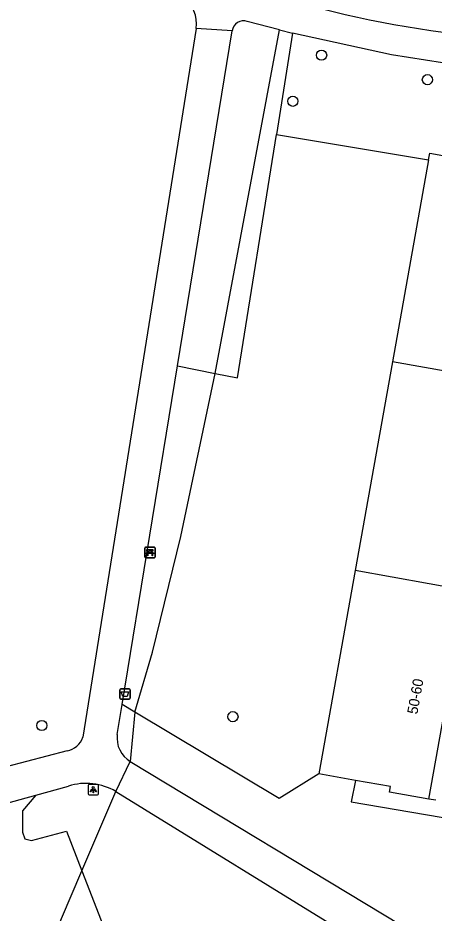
# Model space of a CAD drawing. Extents: x 161402 to 161933, y 381650 to 382313.
# Drawn here: x 161719.2 to 161759.2, y 381796.3 to 381882.3 of the extents above; entities that cross this region are included whole.
import ezdxf

# ---------------------------------------------------------------- set-up
doc = ezdxf.new("R2010")
doc.units = 0
for name, color, linetype in [('IMGEO_Afvalbak', 7, 'Continuous'), ('IMGEO_Bank', 7, 'Continuous'), ('IMGEO_Boom', 7, 'Continuous'), ('IMGEO_Groenvoorziening', 7, 'Continuous'), ('IMGEO_Lichtpunt', 7, 'Continuous'), ('IMGEO_Pand', 7, 'Continuous'), ('IMGEO_Pand_nummerreeks', 7, 'Continuous'), ('IMGEO_Voetpad_gesloten', 7, 'Continuous'), ('IMGEO_Voetpad_open', 7, 'Continuous')]:
    doc.layers.add(name, color=color, linetype=linetype)

msp = doc.modelspace()

# ---------------------------------------------------------------- linework, layer by layer
at = {"layer": 'IMGEO_Afvalbak'}
for p, q in [((161729.01, 381816.99), (161729.01, 381817.79)), ((161729.01, 381817.79), (161729.01, 381816.99)), ((161729.11, 381817.89), (161729.9, 381817.89)), ((161729.9, 381817.89), (161729.11, 381817.89)), ((161730, 381817.79), (161730, 381816.99)), ((161730, 381816.99), (161730, 381817.79)), ((161729.9, 381816.89), (161729.11, 381816.89)), ((161729.11, 381816.89), (161729.9, 381816.89))]:
    msp.add_line(p, q, dxfattribs=at)
msp.add_lwpolyline([(161729.153, 381817.604), (161729.857, 381817.604), (161729.708, 381817.134), (161729.302, 381817.134), (161729.153, 381817.604)], dxfattribs=at)
for centre, start, end in [((161729.11, 381817.79), 90, 180), ((161729.11, 381817.79), 90, 180), ((161729.9, 381817.79), 0, 90), ((161729.9, 381817.79), 360, 90), ((161729.11, 381816.99), 180, 270), ((161729.11, 381816.99), 180, 270), ((161729.9, 381816.99), 270, 0), ((161729.9, 381816.99), 270, 0)]:
    msp.add_arc(centre, 0.1, start, end, dxfattribs=at)
at = {"layer": 'IMGEO_Bank'}
for p, q in [((161731.478, 381831.472), (161732.319, 381831.472)), ((161732.319, 381831.472), (161731.478, 381831.472)), ((161731.403, 381830.547), (161731.403, 381831.388)), ((161731.403, 381831.388), (161731.403, 381830.547)), ((161732.1, 381830.87), (161731.707, 381830.87)), ((161731.712, 381830.978), (161731.712, 381831.084)), ((161731.756, 381831.084), (161731.756, 381830.978)), ((161732.044, 381831.09), (161731.762, 381831.09)), ((161731.762, 381830.972), (161732.044, 381830.972)), ((161732.05, 381830.978), (161732.05, 381831.084)), ((161732.094, 381831.084), (161732.094, 381830.978)), ((161732.403, 381831.397), (161732.403, 381830.556)), ((161732.403, 381830.556), (161732.403, 381831.397)), ((161732.328, 381830.472), (161731.487, 381830.472)), ((161731.487, 381830.472), (161732.328, 381830.472))]:
    msp.add_line(p, q, dxfattribs=at)
for points in [[(161731.65, 381830.87), (161731.508, 381830.87), (161731.62, 381830.972), (161731.706, 381830.972)], [(161731.706, 381831.09), (161731.62, 381831.09), (161731.62, 381831.251), (161732.183, 381831.251), (161732.183, 381831.09), (161732.1, 381831.09)], [(161731.7, 381830.863), (161731.7, 381830.656), (161731.657, 381830.656), (161731.657, 381830.863)], [(161732.1, 381830.972), (161732.183, 381830.972), (161732.295, 381830.87), (161732.156, 381830.87)], [(161732.15, 381830.863), (161732.15, 381830.656), (161732.106, 381830.656), (161732.106, 381830.863)]]:
    msp.add_lwpolyline(points, dxfattribs=at)
for centre, radius, start, end in [((161731.481, 381831.394), 0.0779, 92.4484, 184.28452), ((161731.481, 381831.394), 0.0779, 92.4484, 184.28452), ((161732.325, 381831.394), 0.0779, 2.4484, 94.28452), ((161732.325, 381831.394), 0.0779, 2.4484, 94.28452), ((161731.481, 381830.55), 0.0779, 182.4484, 274.28452), ((161731.481, 381830.55), 0.0779, 182.4484, 274.28452), ((161731.65, 381830.863), 0.00671, 2.89567, 87.10433), ((161731.707, 381830.863), 0.00671, 92.89567, 177.10433), ((161731.705, 381831.083), 0.00671, 2.89567, 87.10433), ((161731.705, 381830.979), 0.00671, 272.89567, 357.10433), ((161731.762, 381831.083), 0.00671, 92.89567, 177.10433), ((161731.762, 381830.979), 0.00671, 182.89567, 267.10433), ((161732.044, 381831.083), 0.00671, 2.89567, 87.10433), ((161732.044, 381830.979), 0.00671, 272.89567, 357.10433), ((161732.101, 381831.083), 0.00671, 92.89567, 177.10433), ((161732.101, 381830.979), 0.00671, 182.89567, 267.10433), ((161732.099, 381830.863), 0.00671, 2.89567, 87.10433), ((161732.156, 381830.863), 0.00671, 92.89567, 177.10433), ((161732.325, 381830.55), 0.0779, 272.4484, 4.28452), ((161732.325, 381830.55), 0.0779, 272.4484, 4.28452)]:
    msp.add_arc(centre, radius, start, end, dxfattribs=at)
at = {"layer": 'IMGEO_Boom'}
for centre in [(161748.379, 381878.735), (161758.532, 381876.381), (161745.615, 381874.307), (161739.871, 381815.204), (161721.521, 381814.349)]:
    msp.add_circle(centre, 0.489, dxfattribs=at)
at = {"layer": 'IMGEO_Groenvoorziening'}
for points in [[(161738.162, 381848.165), (161744.341, 381881.177)], [(161745.595, 381880.853), (161744.038, 381871.1)], [(161738.162, 381848.165), (161740.308, 381847.736), (161744.038, 381871.1)], [(161744.038, 381871.1), (161758.643, 381868.683)], [(161734.546, 381848.887), (161738.162, 381848.165)], [(161730.467, 381815.628), (161732.138, 381821.401), (161734.863, 381832.495), (161738.162, 381848.165)], [(161730.467, 381815.628), (161729.238, 381816.363)], [(161730.467, 381815.628), (161730.018, 381810.901)], [(161748.122, 381809.717), (161744.303, 381807.358), (161730.467, 381815.628)], [(161720.944, 381807.67), (161719.659, 381806.175), (161719.659, 381804.119), (161719.883, 381803.471), (161720.531, 381803.314), (161723.882, 381804.205), (161725.367, 381800.387)], [(161725.367, 381800.387), (161728.625, 381808.023)], [(161702.23, 381724.444), (161705.894, 381734.943), (161712.581, 381759.611), (161715.357, 381771.588), (161718.107, 381785.811), (161721.564, 381791.006), (161723.418, 381795.819), (161725.367, 381800.387)], [(161725.367, 381800.387), (161728.333, 381792.761), (161720.782, 381750), (161715.379, 381719.409), (161702.956, 381716.799)]]:
    msp.add_lwpolyline(points, dxfattribs=at)
at = {"layer": 'IMGEO_Lichtpunt'}
for p, q in [((161725.964, 381808.599), (161725.964, 381807.792)), ((161725.964, 381808.599), (161725.964, 381807.792)), ((161726.866, 381808.694), (161726.058, 381808.694)), ((161726.866, 381808.694), (161726.058, 381808.694)), ((161726.96, 381807.792), (161726.96, 381808.599)), ((161726.96, 381807.792), (161726.96, 381808.599)), ((161726.058, 381807.698), (161726.866, 381807.698)), ((161726.058, 381807.698), (161726.866, 381807.698))]:
    msp.add_line(p, q, dxfattribs=at)
for points in [[(161726.338, 381808.263), (161726.377, 381808.235), (161726.189, 381807.973), (161726.151, 381808), (161726.338, 381808.263)], [(161726.44, 381808.215), (161726.487, 381808.215), (161726.487, 381807.893), (161726.44, 381807.893), (161726.44, 381808.215)], [(161726.55, 381808.235), (161726.588, 381808.262), (161726.775, 381808), (161726.736, 381807.972), (161726.55, 381808.235)]]:
    msp.add_lwpolyline(points, dxfattribs=at)
msp.add_circle((161726.463, 381808.397), 0.0994, dxfattribs=at)
for centre, start, end in [((161726.058, 381808.599), 90, 180), ((161726.058, 381808.599), 90, 180), ((161726.866, 381808.599), 0, 90), ((161726.866, 381808.599), 0, 90), ((161726.058, 381807.792), 180, 270), ((161726.058, 381807.792), 180, 270), ((161726.866, 381807.792), 270, 0), ((161726.866, 381807.792), 270, 360)]:
    msp.add_arc(centre, 0.0946, start, end, dxfattribs=at)
at = {"layer": 'IMGEO_Pand'}
for points in [[(161758.643, 381868.683), (161758.758, 381869.329), (161762.157, 381868.723)], [(161758.643, 381868.683), (161755.181, 381849.282)], [(161755.181, 381849.282), (161751.604, 381829.233)], [(161765.835, 381847.381), (161755.181, 381849.282)], [(161751.604, 381829.233), (161748.122, 381809.717)], [(161762.257, 381827.332), (161751.604, 381829.233)], [(161758.68, 381807.283), (161760.397, 381816.906)], [(161751.647, 381809.088), (161748.122, 381809.717)], [(161758.68, 381807.283), (161754.904, 381807.957), (161754.999, 381808.489), (161751.647, 381809.088)]]:
    msp.add_lwpolyline(points, dxfattribs=at)
at = {"layer": 'IMGEO_Voetpad_gesloten'}
for points in [[(161736.342, 381881.306), (161725.456, 381813.226)], [(161739.797, 381881.069), (161736.342, 381881.306)], [(161744.341, 381881.177), (161741.245, 381881.98)], [(161734.546, 381848.887), (161739.797, 381881.069)], [(161744.341, 381881.177), (161745.595, 381880.853)], [(161778.453, 381875.613), (161778.225, 381875.706), (161764.885, 381877.23), (161755.085, 381878.76), (161745.595, 381880.853)], [(161729.238, 381816.363), (161734.546, 381848.887)], [(161728.768, 381813.48), (161729.238, 381816.363)], [(161723.946, 381811.938), (161714.178, 381809.365), (161688.476, 381802.105), (161686.619, 381801.839), (161684.744, 381801.774), (161679.529, 381802.264), (161660.159, 381804.525), (161632.491, 381807.344)], [(161728.625, 381808.023), (161730.018, 381810.901)], [(161730.018, 381810.901), (161756.079, 381795.155)], [(161720.944, 381807.67), (161724.1, 381808.537)], [(161716.413, 381806.426), (161720.944, 381807.67)], [(161728.625, 381808.023), (161751.894, 381793.676), (161752.712, 381793.202)]]:
    msp.add_lwpolyline(points, dxfattribs=at)
for centre, radius, start, end in [((161733.322, 381881.771), 3.056, 351.2409, 55.6735), ((161773.213, 381979.731), 99.666, 253.48297, 264.46507), ((161740.88, 381880.954), 1.089, 70.39121, 173.96037), ((161731.36, 381813.144), 2.614, 172.61443, 239.10302), ((161723.639, 381813.827), 1.914, 279.23386, 341.69318), ((161725.783, 381803.176), 5.619, 59.61153, 107.42744)]:
    msp.add_arc(centre, radius, start, end, dxfattribs=at)
at = {"layer": 'IMGEO_Voetpad_open'}
for points in [[(161751.647, 381809.088), (161751.227, 381807.036), (161772.812, 381803.355)], [(161759.331, 381807.171), (161758.68, 381807.283)]]:
    msp.add_lwpolyline(points, dxfattribs=at)

# ---------------------------------------------------------------- texts
at = {"layer": 'IMGEO_Pand_nummerreeks'}
msp.add_text('50-60', height=1, rotation=79.88417, dxfattribs=at).set_placement((161757.565, 381815.384))

doc.saveas('drawing.dxf')
